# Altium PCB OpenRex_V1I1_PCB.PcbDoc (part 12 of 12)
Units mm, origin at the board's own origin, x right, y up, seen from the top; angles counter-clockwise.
Board outline 70 x 95 mm, 10 copper layers (L1, L2, L3, L4 (PWR), L5 (PWR), L6 (PWR), L7 (PWR), L8, L9, L10), stack 1.632 mm thick; 1080 components, 708 nets, 3831 pads, 2373 vias.
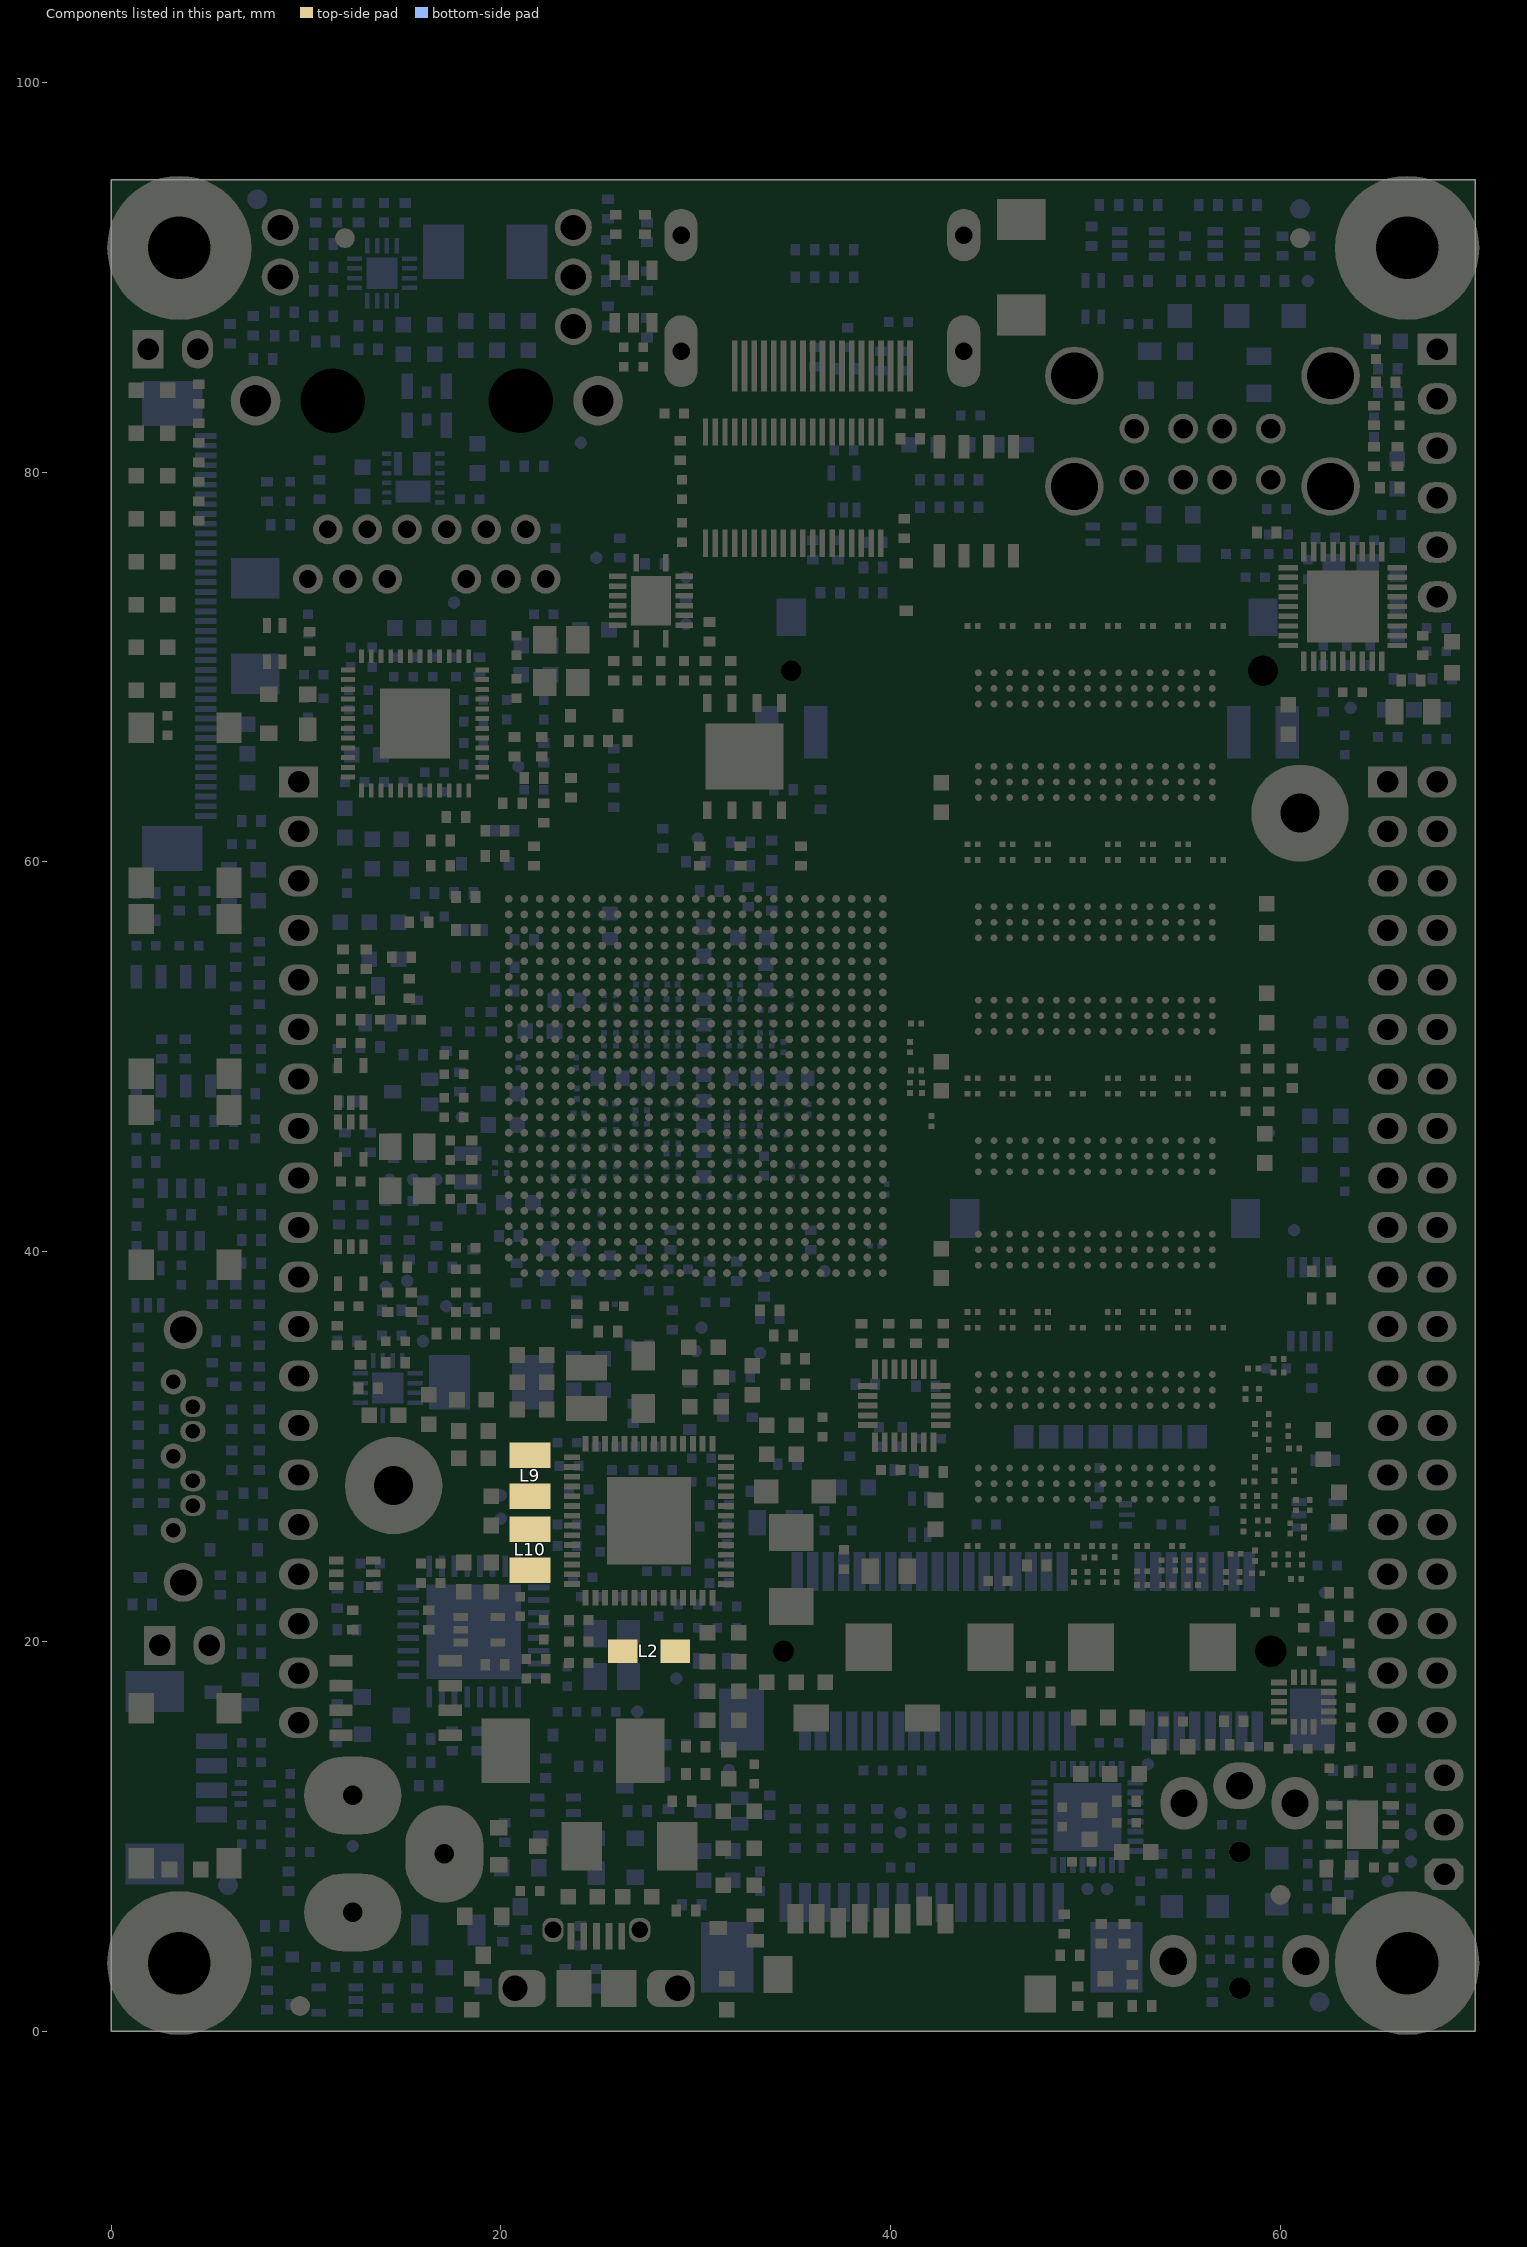
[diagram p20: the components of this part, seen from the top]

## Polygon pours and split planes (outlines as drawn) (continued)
GND on L10 "L10" (solid, remove dead copper, pour order 579): 23.6,30.5 24.1,30.5 24.3,30.3 24.5,30.3 25.2,30.3 25.2,29.7 25,29.5 24.7,29.2 24.25,28.75 23.7,28.75 23.7,29.4 23.6,29.5
+VIN_4V2 on L10 "L10" (solid, remove dead copper, pour order 578): 25.4,28.5 29.1,28.5 29.1,29 28.8,29 28.7,29.1 28.2,29.6 27.8,29.6 27.3,29.6 27.2,29.7 27.2,30.3 25.6,30.3 25.6,29.8 25.3,29.5 25.3,28.6
+3V3 on L10 "L10" (solid, remove dead copper, pour order 577): 38.2,29.8 38.2,29.2 37.9,29.2 37.8,29.1 37.8,27.5 36.9,27.5 36.9,29.8 38.2,29.8
+3V3_GYRO on L10 "L10" (solid, remove dead copper, pour order 576): 38.4,27.5 39.3,27.5 39.3,28 39.7,28.4 39.8,28.5 40.5,28.5 40.5,29.1 40.9,29.5 40.9,30.3 39.1,30.3 38.9,30.1 38.9,29.4 38.9,29.2 38.5,28.8 38.4,28.7
GND on L10 "L10" (solid, remove dead copper, pour order 575): 24.8,34.9 25.8,34.9 26.2,34.5 26.2,32.7 26,32.5 24.8,32.5
+1V375_SOC on L10 "L10" (solid, remove dead copper, pour order 574): 20.6,34.7 20.6,31.9 22.8,31.9 23.4,31.3 23.9,31.3 23.9,32.2 24.2,32.5 24.2,34.9 23.4,34.9 23.2,35.1 21,35.1 20.6,34.7
+VIN_4V2 on L10 "L10" (solid, remove dead copper, pour order 573): 15.4,32.3 14.9,31.8 14.9,31.6 14.7,31.6 14.4,31.6 14.3,31.5 14.3,30.8 14.4,30.7 15.3,30.7 16,31.4 16,32.3
PHASE_1V375 on L10 "L10" (solid, remove dead copper, pour order 572): 15.7,32.6 15.6,32.7 15.6,33.8 15.6,34 16.3,34.7 18.4,34.7 18.4,31.9 16.3,31.9 16.3,32.3 16,32.6 15.7,32.6 15.6,32.7
+VIN_5V on L10 "L10" (solid, remove dead copper, pour order 570): 19 vertices, not listed, extent 21.4,8.9 22.9,10.8
+3V3_MCU on L10 "L10" (solid, remove dead copper, pour order 569): 23.6,16.1 25.2,16.1 25.2,16.6 25,16.8 24.6,17.2 23.5,17.2 23.4,17.1 23.4,17 23.4,16.8 23.5,16.7 23.6,16.6
GND on L10 "L10" (solid, remove dead copper, pour order 568): 19.8,5.3 20.4,5.3 20.9,5.8 21.4,5.8 21.4,6.8 20.7,7.5 20.5,7.5 20,7 20,6.7 20,6.5 19.9,6.4 19.8,6.3 19.8,5.5
+V_INPUT on L10 "L10" (solid, remove dead copper, pour order 567): 16.3,4.4 16.3,6.5 16,6.8 15.4,6.8 15.1,6.5 15.1,4.4 16.3,4.4
GND on L10 "L10" (solid, remove dead copper, pour order 566): 21 vertices, not listed, extent 0.7,7.1 4.4,10.3
GND on L10 "L10" (solid, remove dead copper, pour order 565): 1.1,19.1 1.6,18.6 4,18.6 4.4,18.2 4.4,16.6 3.6,15.8 3.1,15.3 1.6,15.3 0.9,15.3 0.7,15.5 0.7,18.8 1,19.1
GND on L10 "L10" (solid, remove dead copper, pour order 564): 22 vertices, not listed, extent 0.4,59.2 5.2,62.4
SPLIT_R on L10 "L10" (solid, remove dead copper, pour order 563): 4.8,49.1 5.4,49.1 5.9,48.6 6.1,48.4 6.5,48.4 6.7,48.4 6.7,47.8 5.5,47.8 5.4,47.9 4.8,47.9 4.8,49.1
+3V3 on L10 "L10" (solid, remove dead copper, pour order 562): 7.2,58.4 8.2,58.4 8.5,58.1 8.5,57.7 7.7,56.9 7.5,56.9 7.2,57.2 7.1,57.3 7.1,58.4
+3V3_CSI1 on L10 "L10" (solid, remove dead copper, pour order 561): 4.8,63 4.8,62.2 5.3,62.2 5.4,62.1 5.6,61.9 5.6,59.3 5.6,57.6 6.5,57.6 6.5,61.3 6.2,61.6 6.2,62.2 6.2,62.4 5.6,63 4.8,63
GND on L10 "L10" (solid, remove dead copper, pour order 560): 6.9,61.2 7.5,61.2 8,60.7 8,59.1 7.5,58.6 7.1,58.6 7.1,59.8 7.1,60 7,60.1 6.9,60.2 6.9,61.2
GND on L10 "L10" (solid, remove dead copper, pour order 559): 28.9,39.4 28.9,37.7 28.3,37.7 28.3,38.3 27.8,38.8 27.8,39.3 27.9,39.4
GND on L10 "L10" (solid, remove dead copper, pour order 558): 19.6,42.9 20.5,42.9 20.5,42.2 20.8,41.9 20.9,41.8 20.9,41.6 20.8,41.5 19.9,41.5 19.6,41.8 19.6,42 19.6,42.9
+NVCC_CSI on L10 "L10" (solid, remove dead copper, pour order 557): 27 vertices, not listed, extent 29.5,39.2 32.7,43.5
+HDMI_VPH on L10 "L10" (solid, remove dead copper, pour order 556): 27 vertices, not listed, extent 28.7,39.2 31,44
+HDMI_VP on L10 "L10" (solid, remove dead copper, pour order 555): 29 vertices, not listed, extent 27.9,40.8 29,44
+NVCC_MIPI on L10 "L10" (solid, remove dead copper, pour order 554): 27.3,44 27.3,43.7 26.9,43.3 26.5,42.9 26.5,41.5 26.5,40.2 26.9,39.8 27.5,39.8 27.8,40.1 27.8,40.8 27.8,42.4 27.7,42.5 27.7,44
+2V5 on L10 "L10" (solid, remove dead copper, pour order 553): 35.6,40.4 36.8,40.4 37.7,39.5 37.7,39 37.6,38.9 37.4,38.7 36.5,38.7 35.6,39.6 35.6,40.4
GND on L10 "L10" (solid, remove dead copper, pour order 511): 45.4,94 48.2,94 48.6,93.6 48.6,92.3 48.2,91.9 45.4,91.9
PHASE_3V3_HDR on L10 "L10" (solid, remove dead copper, pour order 514): 15.35,89.85 18.1,89.85 18.1,92.7 16,92.7 15.4,92.1 15.3,92 15.3,90 15.3,89.9
+VIN_4V2 on L10 "L10" (solid, remove dead copper, pour order 515): 17 vertices, not listed, extent 14.05,86.8 17.6,89.55
GND on L10 "L10" (solid, remove dead copper, pour order 516): 14.6,86.5 15.4,86.5 15.6,86.3 15.8,86.3 16,86.3 16.2,86.5 17,86.5 17,85.6 16.7,85.3 15,85.3 14.9,85.3 14.6,85.6
GND on L10 "L10" (solid, remove dead copper, pour order 517): 19 vertices, not listed, extent 17.4,85.3 22.3,87
+3V3_HDR on L10 "L10" (solid, remove dead copper, pour order 518): 22 vertices, not listed, extent 17.8,87.3 22.4,92.7
GND on L10 "L10" (solid, remove dead copper, pour order 519): 25 vertices, not listed, extent 0.5,80.9 5.3,85.3
GND on L10 "L10" (solid, remove dead copper, pour order 520): 12,80.7 12,80.3 12.5,79.8 13.3,79.8 13.5,80 13.5,81.1 13.2,81.1 13.1,81.1 12.9,80.9 12.8,80.8 12.7,80.8 12.2,80.8 12,80.6
+3V3 on L10 "L10" (solid, remove dead copper, pour order 521): 11.5,80.8 11.6,80.7 11.6,80.5 11.5,80.4 11.4,80.3 10.5,80.3 10,80.3 9.8,80.5 9.8,80.7 10,80.9 10.3,80.9 11.4,80.9 11.5,80.8
+VIN_4V2 on L10 "L10" (solid, remove dead copper, pour order 522): 10.1,79.1 10.3,78.9 10.4,78.9 11.1,78.9 11.3,79.1 11.5,79.1 11.6,79 11.6,78.8 11.1,78.3 10.3,78.3 9.8,78.8 9.8,79 9.9,79.1
+VIN_ETH on L10 "L10" (solid, remove dead copper, pour order 523): 10.4,79.9 11.9,79.9 12.6,79.2 13.3,79.2 14,78.5 14,78.4 13.9,78.3 12.5,78.3 11.5,79.3 10.4,79.3
SW_EP on L10 "L10" (solid, remove dead copper, pour order 524): 13.9,81 13.9,81.1 15,81.1 15,79.8 14.5,79.8 14.4,79.7 14.4,79.4 14.4,79.3 13.9,79.3
+1V2_REG on L10 "L10" (solid, remove dead copper, pour order 525): 30 vertices, not listed, extent 15.5,78.3 20.5,81.1
+1V2_ETH on L10 "L10" (solid, remove dead copper, pour order 526): 20.9,80 21.5,80 21.5,80.6 21.8,80.9 21.8,81.1 21.7,81.2 20.7,81.2 20.6,81.1 20.6,80.9 20.9,80.6
+1V2_PMIC on L10 "L10" (solid, remove dead copper, pour order 527): 22,80 22,81.2 22.8,82 24.2,82 24.4,81.8 24.5,81.7 24.5,81.3 23.2,80
GND on L10 "L10" (solid, remove dead copper, pour order 528): 22.1,71.5 23.4,71.5 24.3,70.6 24.3,70.2 23.3,69.2 22.1,69.2
+1V2_ETH_AVDDL_PLL on L10 "L10" (solid, remove dead copper, pour order 529): 30 vertices, not listed, extent 18.8,66.9 22.5,70
GND on L10 "L10" (solid, remove dead copper, pour order 530): 9.8,67.1 10.4,67.1 10.9,67.6 10.9,67.8 10.7,68 10.3,68 10.2,68.1 10.2,68.7 9.6,68.7 9.6,67.3
+1V2_ETH_DVDDL on L10 "L10" (solid, remove dead copper, pour order 531): 44 vertices, not listed, extent 11.3,62.3 16.4,67.5
GND on L10 "L10" (solid, remove dead copper, pour order 532): 6.2,73.5 8.7,73.5 8.7,75.4 9.2,75.9 9.2,76.1 9.1,76.2 8,76.2 7.4,76.2 6.8,75.6 6.2,75.6
+5V_HDR_J1 on L10 "L10" (solid, remove dead copper, pour order 533): 22 vertices, not listed, extent 6.2,63.3 10.6,70.7
+5V on L10 "L10" (solid, remove dead copper, pour order 534): 7.3,68.1 7.5,68.1 8,67.6 8,67.2 7.4,66.6 6.9,66.6 6.6,66.6 6.6,67.4
+VIN_5V on L10 "L10" (solid, remove dead copper, pour order 535): 7.4,63.6 7.4,64.5 6.4,64.5 6,64.9 5.7,64.9 5.7,63.8 5.9,63.6
+3V3 on L10 "L10" (solid, remove dead copper, pour order 536): 14.3,56.5 15.2,56.5 15.2,57.9 13.8,57.9 13.8,57.6 13.9,57.5 14,57.4 14.2,57.4 14.3,57.3
+3V3_HDR on L10 "L10" (solid, remove dead copper, pour order 537): 11.1,55.9 12.1,55.9 12.2,56 12.2,57.3 11.3,57.3 11.1,57.1 11.1,55.9
+3V3_HDR_J1 on L10 "L10" (solid, remove dead copper, pour order 538): 19 vertices, not listed, extent 9.1,48.3 13.7,57.3
GND on L10 "L10" (solid, remove dead copper, pour order 539): 14.3,55.4 14.8,55.4 15.2,55.8 15.6,55.8 15.6,54.7 15,54.1 14.4,54.1 14.3,54.2 14.3,55.4
GND on L10 "L10" (solid, remove dead copper, pour order 540): 21.7,51.7 21.7,50.9 20.7,50.9 20.2,50.4 20.1,50.3 20,50.3 19.8,50.5 19.8,50.7 20.2,51.1 20.8,51.7 21.7,51.7
+1V375_CORE on L10 "Power plane" (solid, pour order 411): 21 vertices, not listed, extent 27.8,44.8 33,45.5
GND on L10 "Power plane" (solid, pour order 414): 23 vertices, not listed, extent 26.7,44.7 29.7,46.3
+1V2_VDD_ARM_CAP on L10 "Power plane" (solid, pour order 421): 29 vertices, not listed, extent 26.2,46.05 31.8,46.8
GND on L10 "Power plane" (solid, pour order 425): 23 vertices, not listed, extent 25.7,46.6 28.9,48.2
GND on L10 "Power plane" (solid, pour order 433): 27 vertices, not listed, extent 28.5,47.2 32.2,49.4
GND on L10 "Power plane" (solid, pour order 437): 31.2,47.3 32.6,47.3 33.5,47.3 33.5,47.2 33.5,46.3 32.9,46.3 32.1,46.3 32.1,46.7 31.9,46.9 31.6,46.9 31.4,46.9 31.2,47.1
+1V1_VDDSOC_CAP on L10 "Power plane" (solid, pour order 442): 19 vertices, not listed, extent 32.1,47.5 33.5,50.2
+1V375_CORE on L10 "Power plane" (solid, pour order 446): 23 vertices, not listed, extent 25.7,48.5 29.8,50.2
+1V2_VDD_ARM_CAP on L10 "Power plane" (solid, pour order 450): 26.2,48.1 26.2,48.2 26.3,48.3 26.4,48.3 27,48.3 27.1,48.4 27.1,49.3 27.3,49.3 27.9,49.3 27.9,48.5 28.1,48.3 28.1,48 28,47.9 27.7,47.6 26.7,47.6
GND on L10 "Power plane" (solid, pour order 453): 31 vertices, not listed, extent 24.7,50.3 29.8,51.4
GND on L10 "Power plane" (solid, pour order 455): 17 vertices, not listed, extent 31.1,50.3 35.4,50.9
+1V375_SOC on L10 "Power plane" (solid, pour order 456): 62 vertices, not listed, extent 23.7,50.6 33.5,53.3
+VDDPU on L10 "Power plane" (solid, pour order 458): 30 vertices, not listed, extent 25.7,51.4 30.8,52.8
GND on L10 "Power plane" (solid, pour order 459): 40 vertices, not listed, extent 24.6,52.6 30.8,53.9
GND on L10 "Power plane" (solid, pour order 462): 26 vertices, not listed, extent 34.5,45.8 36.1,49.3
GND on L10 "L10" (solid, remove dead copper, pour order 541): 25.3,48.5 25.3,49.3 24.3,49.3 24,49.6 23.7,49.6 23.7,48.2 24.1,48.2 24.2,48.2 24.5,48.5 25.3,48.5
+3V3 on L10 "L10" (solid, remove dead copper, pour order 542): 25 vertices, not listed, extent 22.3,49.6 25.5,51.9
+3V3 on L10 "L10" (solid, remove dead copper, pour order 543): 27 vertices, not listed, extent 27.3,53.55 30.8,55.55
GND on L10 "L10" (solid, remove dead copper, pour order 544): 32.95,53.55 32.95,54.2 33.15,54.4 34,54.4 34.05,54.45 34.05,56.5 33.25,56.5 33.25,55.75 32.9,55.4 32.45,54.95 32.45,53.9 32.45,53.75 32.65,53.55
+1V5_DDR on L10 "L10" (solid, remove dead copper, pour order 545): 21 vertices, not listed, extent 31.05,52.25 34,53.8
GND on L10 "L10" (solid, remove dead copper, pour order 546): 27 vertices, not listed, extent 31.1,51.6 35.1,53.3
+1V5_DDR on L10 "L10" (solid, remove dead copper, pour order 547): 34.75,52.8 34.25,52.3 34.25,51.9 34.25,51.6 34.05,51.4 33.75,51.4 33.75,51.05 34.45,51.05 34.6,51.2 34.9,51.5 34.9,52 34.9,52.3 35.05,52.45 35.05,52.8
+LVDS_2V5 on L10 "L10" (solid, remove dead copper, pour order 548): 25 vertices, not listed, extent 33.2,40.8 36.2,44.2
+1V5_DDR on L10 "L10" (solid, remove dead copper, pour order 549): 28 vertices, not listed, extent 33.7,44.2 35.1,50.4
GND on L10 "Power plane" (solid, pour order 409): 46 vertices, not listed, extent 25.7,42.6 33,45
GND on L10 "L10" (solid, remove dead copper, pour order 550): 25 vertices, not listed, extent 24.1,44.2 25.5,46.4
GND on L10 "L10" (solid, remove dead copper, pour order 551): 23.9,44 23.9,42.9 23.3,42.9 22.5,43.7 22.5,44 22.9,44 23.1,44.2 23.3,44.2 23.4,44.1 23.5,44 23.9,44
+1V1_NVCC_PLL_OUT on L10 "L10" (solid, remove dead copper, pour order 552): 21 vertices, not listed, extent 20.9,42.1 23.4,45
GND on L10 "L10" (solid, remove dead copper, pour order 397): 24.7,13.9 25.2,13.9 25.5,14.2 26.8,14.2 26.8,13.5 26,13.5 25.8,13.3 25.1,12.6 24.6,12.6 24.5,12.6 24.4,12.7 24.4,12.9 24.4,13 24.7,13.3
GND on L10 "L10" (solid, remove dead copper, pour order 400): 26.4,10.3 26.4,9.5 26.7,9.2 27.2,8.7 27.7,8.7 27.8,8.8 27.8,10.3 27.6,10.5 26.6,10.5 26.4,10.3
GND on L10 "L10" (solid, remove dead copper, pour order 319): 48.5,24.6 49.5,24.6 49.6,24.5 49.6,24.2 49.2,23.8 49.1,23.7 49.1,23.5 48.5,23.5
GND on L2 (split plane): 69.898,0.102 0.102,0.102 0.102,94.898 69.898,94.898
GND on L9 (split plane): 69.898,0.102 0.102,0.102 0.102,94.898 69.898,94.898

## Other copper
L10:
  rectangle net PWM2_OUT_R: 61.7,50.3 62.35,50.95
  region net UART4_TXD: 63.5,50.95 62.85,50.95 62.85,50.3 63.5,50.3
  region net UART4_TXD_R: 62.85,52.1 62.85,51.45 63.5,51.45 63.5,52.1
  region net GPIO_OR_PWM_2: 61.7,52.1 61.7,51.45 62.35,51.45 62.35,52.1
  region: 1344 vertices and 0 holes, not listed, extent 31.797,93.426 33.878,94.403
  region: 1381 vertices and 0 holes, not listed, extent 32.34,91.702 33.939,93.239
  region: 2099 vertices and 0 holes, not listed, extent 30.813,91.665 32.707,94.4

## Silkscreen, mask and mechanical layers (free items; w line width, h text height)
Top Overlay:
  text ".VersionRevision" at 52.7,77.2 h2.5 r180
  text "5" at 4.7,75.9 h2.2 r270
  text ".Project" at 57,74.8 h3.35 r180
  text "6" at 4.7,73.7 h2.2 r270
  text "7" at 4.7,71.5 h2.2 r270
  text "8" at 4.7,69.3 h2.2 r270
  text "+" at 3.1,57.8 h3
  text "(c) 2016" at 61.8,52 h2.2 r90
  text "-" at 3,49.6 h3.5 r270
  text "FEDEVEL Academy" at 63.5,41 h2.2 r90
  text "H" at 3,39.9 h2.5 r270
  text "R" at 3,17.5 h2.5 r270
Bottom Overlay:
  lines w0.254: 26.644,77.999 26.644,80.499 ; 29.644,77.999 29.644,80.499 ; 32.644,77.999 32.644,80.499 ; 23.644,77.999 35.644,77.999 35.644,80.499 23.644,80.499 23.644,77.999
  text "MODBOX" at 35.6,81.5 h2.3
  text "D" at 25.944,78.499 h2.5
  text "C" at 28.944,78.499 h2.5
  text "B" at 31.944,78.499 h2.5
  text "A" at 34.944,78.499 h2.5
  text "Learn Schematic" at 55.8,68 h2.5
  text "and PCB Design" at 55.6,65.4 h2.5
  text "ONLINE at" at 52.4,62.8 h2.5
  text "FEDEVEL Academy" at 57.3,60.2 h2.5
  text "Do you want to learn how to" at 59.8,55 h2
  text "design boards like this?" at 58.2,52.7 h2
  text "Go to: fedevel.com/academy" at 60.2,50.4 h2
Bottom Paste:
  rectangle: 61.7,51.45 62.35,52.1
  rectangle: 62.85,51.45 63.5,52.1
  rectangle: 62.85,50.3 63.5,50.95
  rectangle: 61.7,50.3 62.35,50.95
Bottom Solder:
  drawing of 7 lines, arcs and shapes, not listed
Manufacturing Notes:
  circle w1: c176.75,149.25 r0.25
  circle w1: c176.75,108.25 r0.25
  circle w1: c260.75,108.25 r0.25
  circle w1: c260.75,149.25 r0.25
  lines w0.2: 142.5,102.5 178.75,102.5 ; 142.5,105 178.75,105 ; 142.5,152.5 178.75,152.5 ; 142.5,155 178.75,155 ; 144,101.5 145,102.5 146,101.5 ; 144,106 145,105 146,106 ; 144,151.5 145,152.5 146,151.5 ; 144,156 145,155 146,156 ; 145,95 145,162.5 ; 163.75,128.75 165,128.75 ; 175,108.75 176.25,108.75 ; 175,148.75 176.25,148.75 ; 176.25,110 176.25,108.75 ; 176.25,147.5 176.25,148.75 ; 180,108.75 180,110 ; 180,152.5 180,164 ; 181,161.5 180,162.5 ; 181,163.5 180,162.5 ; 181.25,110 180,110 ; 197.5,91 197.5,92.5 ; 213.75,102.5 213.75,103.75 ; 213.75,110 215,110 ; 213.75,155 213.75,153.75 ; 214,161.5 215,162.5 ; 214,163.5 215,162.5 ; 215,102.5 227.5,102.5 ; 215,103.75 213.75,103.75 ; 215,105 227.5,105 ; 215,108.75 215,110 ; 215,153.75 213.75,153.75 ; 215,155 227.5,155 ; 215,164 215,152.5 227.5,152.5 ; 218.75,93.75 218.75,98.75 ; 218.75,163.75 218.75,158.75 ; 222.5,103.75 223.75,103.75 ; 222.5,108.75 222.5,110 ; 222.5,152.5 222.5,164 ; 222.5,153.75 223.75,153.75 ; 223.5,161.5 222.5,162.5 ; 223.5,163.5 222.5,162.5 ; 223.75,102.5 223.75,103.75 ; 223.75,110 222.5,110 ; 223.75,155 223.75,153.75 ; 240,91 240,92.5 ; 256.25,110 257.5,110 ; 256.5,161.5 257.5,162.5 ; 256.5,163.5 257.5,162.5 ; 257.5,108.75 257.5,110 ; 257.5,152.5 257.5,164 ; 261.25,110 261.25,108.75 ; 261.25,147.5 261.25,148.75 ; 262.5,108.75 261.25,108.75 ; 262.5,148.75 261.25,148.75 ; 282.5,128.75 281.25,128.75 ; 165,128.75 167,126.75 ; 165,128.75 167,130.75 167,139.5 176.25,148.75 ; 167,126.75 167,118 176.25,108.75 ; 167,126.75 167,126.75 ; 180,110 197.5,92.5 ; 180,162.5 215,162.5 ; 197.5,92.5 215,110 ; 213.75,103.75 218.75,98.75 ; 213.75,153.75 218.75,158.75 ; 218.75,98.75 223.75,103.75 ; 218.75,158.75 223.75,153.75 ; 222.5,110 240,92.5 ; 222.5,162.5 257.5,162.5 ; 240,92.5 257.5,110 ; 261.25,108.75 281.25,128.75 ; 261.25,148.75 281.25,128.75
  lines w0.254: -6.5,-82 86,-82 ; -6.5,-81.925 -6.5,-71.925 ; -6.5,-62 86,-62 ; 33.5,-72 33.5,-62 ; 68.5,-62 68.5,-54.5 ; 86,-81.925 86,-71.925 ; -6.5,-72 -6.5,-54.5 86,-54.5 86,-72 -6.5,-72
  lines w0.4: 142.524,54.2 291.976,54.2 ; 142.524,61.16 291.976,61.16 ; 291,70.5 143.25,70.5 ccw(c143.25,68.25) 141,68.25 141,-34.75 ccw(c143.25,-34.75) 143.25,-37 291.25,-37 ccw(c291.25,-34.75) 293.5,-34.75 293.5,68.25 ccw(c291.25,68.25) 291.25,70.5
  lines w0.5: 180,100 180,102.5 ; 180,105 180,152.5 ; 180,155 180,157.5 ; 215,100 215,102.5 ; 215,105 215,152.5 ; 215,155 215,157.5 ; 216.096,102.5 ccw(c216.096,103.75) 216.096,105 ; 216.096,152.5 ccw(c216.096,153.75) 216.096,155 ; 216.25,102.5 178.75,102.5 cw(c178.75,103.75) 178.75,105 216.25,105 ; 216.25,152.5 178.75,152.5 cw(c178.75,153.75) 178.75,155 216.25,155 ; 221.25,102.5 258.75,102.5 ccw(c258.75,103.75) 258.75,105 221.25,105 ; 221.25,152.5 258.75,152.5 ccw(c258.75,153.75) 258.75,155 221.25,155 ; 221.404,102.5 cw(c221.404,103.75) 221.404,105 ; 221.404,152.5 cw(c221.404,153.75) 221.404,155 ; 222.5,100 222.5,102.5 ; 222.5,105 222.5,152.5 ; 222.5,155 222.5,157.5 ; 257.5,100 257.5,102.5 ; 257.5,105 257.5,152.5 ; 257.5,155 257.5,157.5 ; 263.75,100 173.75,100 173.75,157.5 263.75,157.5 263.75,100.154
  text "Board info" at 141,258 h1.52
  text "Minimum Track: 100um" at 141,255.5 h1.52
  text "Minimum Gap: 100um" at 141,253 h1.52
  text "Minimum Through Hole VIA: 0.45mm (pad) / 0.2mm (drill). Drilling: L1-L10" at 141,250.5 h1.52
  text "1. REMOVE ALL NON-FUNCTIONAL INNER LAYER PADS." at 141,245.5 h1.52
  text "2. THIS BOARD CONTAINS IMPEDANCE CONTROLLED TRACKS, TRACK AND GAP SIZES ARE AS FOLLOWS:" at 141,240.5 h1.52
  text "TYPE;" at 146,235.5 h1.52
  text "Impedance;" at 158.5,235.5 h1.52
  text "Layer (Reference);" at 181,235.5 h1.52
  text "Width (um);" at 216,235.5 h1.52
  text "Gap (um);" at 236,235.5 h1.52
  text "DIFF;" at 146,230.5 h1.52
  text "90ohm;" at 158.5,230.5 h1.52
  text "L1(L2), L10(L9);" at 181,230.5 h1.52
  text "114" at 216,230.5 h1.52
  text "160" at 236,230.5 h1.52
  text "DIFF;" at 146,228 h1.52
  text "90ohm;" at 158.5,228 h1.52
  text "L3(L2,L4), L8(L9,L7);" at 181,228 h1.52
  text "130" at 216,228 h1.52
  text "190" at 236,228 h1.52
  text "DIFF;" at 146,223 h1.52
  text "100ohm;" at 158.5,223 h1.52
  text "L1(L2), L10(L9);" at 181,223 h1.52
  text "100" at 216,223 h1.52
  text "220" at 236,223 h1.52
  text "DIFF;" at 146,220.5 h1.52
  text "100ohm;" at 158.5,220.5 h1.52
  text "L3(L2,L4), L8(L9,L7);" at 181,220.5 h1.52
  text "110" at 216,220.5 h1.52
  text "210" at 236,220.5 h1.52
  text "SE;" at 146,215.5 h1.52
  text "50ohm;" at 158.5,215.5 h1.52
  text "L1(L2), L10(L9);" at 181,215.5 h1.52
  text "114" at 216,215.5 h1.52
  text "SE;" at 146,213 h1.52
  text "50ohm;" at 158.5,213 h1.52
  text "L3(L2,L4), L8(L9,L7);" at 181,213 h1.52
  text "120" at 216,213 h1.52
  text "3. FINISHED PANEL THICKNESS IS NOT CRITICAL: TO BE APPROXIMATELY 1.6mm" at 141,208 h1.52
  text "4. BOARD FINISH: IMMERSION Au/ELECTROLESS Ni; 0.05-0.12 um GOLD; 3-6um NICKEL" at 141,203 h1.52
  text "5. SOLDER RESIST: APPLY TO BOTH SIDES COLOUR - NAVY BLUE" at 141,198 h1.52
  text "6. COMPONENT IDENT: COLOUR TO BE WHITE" at 141,193 h1.52
  text "7. PANELIZE THE BOARD (2PCS PER PANEL). PLACE FIDUCIALS ON THE PANEL STRIPS AS FOLLOWS:" at 141,188 h1.52
  text "- FIDUCIAL DIAMTER 1-1.5MM, SOLDER MASK OPENING AT LEAST 1MM GREATER THAN FIDUCIAL" at 146,185.5 h1.52
  text "- MINIMUM 4MM DISTANCE FROM THE PANEL EDGE" at 146,183 h1.52
  text "- 3 FIDUCIALS SHOULD LIE ON TWO LINES THAT INTERSECT AT A RIGHT ANGLE" at 146,180.5 h1.52
  text "- PLACE ONE FIDUCIAL INTO EACH PANEL CORNER (FOUR ON THE TOP AND FOUR ON THE BOTTOM LAYER)" at 146,178 h1.52
  text "PANEL DRAWING (NOT IN SCALE):" at 145.254,172.754 h1.52
  text "- NOT SPECIFIED DIMENSIONS ARE NOT CRITICAL. CAN BE CHOSEN BY PCB MANUFACTURER" at 145.254,170.254 h1.52
  text "CUT-OUT" at 214.004,165.254 h1.52
  text "70mm" at 194.75,163.75 h1.52
  text "70mm" at 237.25,163.75 h1.52
  text "5mm" at 143.75,157.5 h1.52 r90
  text "Files" at -4,150.5 h1.52
  text "*.GTO - Top Overlay" at -4,148 h1.52
  text "*.GTP - Top Paste" at -4,145.5 h1.52
  text "*.GTS - Top Solder" at -4,143 h1.52
  text "*.GTL - L1 (Positive)" at -4,140.5 h1.52
  text "*.GP1 - L2 (Negative)" at -4,138 h1.52
  text "*.G1 - L3 (Positive)" at -4,135.5 h1.52
  text "*.G2 - L4 (PWR) (Positive)" at -4,133 h1.52
  text "*.G3 - L5 (PWR) (Positive)" at -4,130.5 h1.52
  text "FIDUCIALS" at 148.354,128.404 h1.52
  text "*.G4 - L6 (PWR) (Positive)" at -4,128 h1.52
  text "FIDUCIALS" at 285.354,127.654 h1.52
  text "PCB" at 190,127.5 h5.08
  text "PCB" at 232.5,127.5 h5.08
  text "95mm" at 143.75,126.25 h1.52 r90
  text "*.G5 - L7 (PWR) (Positive)" at -4,125.5 h1.52
  text "*.G6 - L8 (Positive)" at -4,123 h1.52
  text "*.GP2 - L9 (Negative)" at -4,120.5 h1.52
  text "*.GBL - L10 (Positive)" at -4,118 h1.52
  text "*.GBS - Bottom Solder" at -4,115.5 h1.52
  text "*.GBP - Bottom Paste" at -4,113 h1.52
  text "*.GBO - Bottom Overlay" at -4,110.5 h1.52
  text "*.GM3 - Manufacturing Notes" at -4,108 h1.52
  text "*.GM4 - License" at -4,105.5 h1.52
  text "*.GM6 - Mechanical Drawing" at -4,103 h1.52
  text "*.GM28 - Board Outline" at -4,100.5 h1.52
  text "5mm" at 143.75,96.25 h1.52 r90
  text "CUT-OUT" at 213.75,91.25 h1.52
  text "V-CUT" at 194.104,87.654 h1.52
  text "V-CUT" at 236.604,87.654 h1.52
  text "Layer Stack Up Detail for: OpenRex V1I1_PCB.PcbDoc" at 142.524,64.75 h1.6
  text "Layer" at 142.524,58.56 h1.6
  text "Gerber" at 187.629,58.56 h1.6
  text "Copper" at 210.818,58.56 h1.6
  text "Dielectric" at 234.119,58.56 h1.6
  text "Dielectric" at 261.619,58.56 h1.6
  text "Name" at 142.524,55.36 h1.6
  text "Document" at 187.629,55.36 h1.6
  text "Thickness" at 210.818,55.36 h1.6
  text "Height" at 234.119,55.36 h1.6
  text "Constant" at 261.619,55.36 h1.6
  text "Top Solder Mask" at 142.524,50.193 h2.25
  text "(.GTS)" at 187.629,50.193 h2.25
  text "43um" at 212.629,42.693 h2.25
  text "L1" at 142.524,42.578 h2.25
  text "(.GTL)" at 187.629,42.578 h2.25
  text "74um" at 235.129,38.943 h2.25
  text "3.95" at 262.629,38.943 h2.25
  text "18um" at 212.629,35.193 h2.25
  text "L2" at 142.524,34.963 h2.25
  text "(.GP1)" at 187.629,34.963 h2.25
  text "102um" at 235.129,31.443 h2.25
  text "4.12" at 262.629,31.443 h2.25
  text "18um" at 212.629,27.693 h2.25
  text "L3" at 142.524,27.348 h2.25
  text "(.G1)" at 187.629,27.348 h2.25
  text "282um" at 235.129,23.943 h2.25
  text "4.06" at 262.629,23.943 h2.25
  text "18um" at 212.629,20.193 h2.25
  text "L4 (PWR)" at 142.524,19.733 h2.25
  text "(.G2)" at 187.629,19.733 h2.25
  text "102um" at 235.129,16.443 h2.25
  text "4.12" at 262.629,16.443 h2.25
  text "18um" at 212.629,12.693 h2.25
  text "L5 (PWR)" at 142.524,12.233 h2.25
  text "(.G3)" at 187.629,12.233 h2.25
  text "282um" at 235.129,8.943 h2.25
  text "4.06" at 262.629,8.943 h2.25
  text "18um" at 212.629,5.193 h2.25
  text "L6 (PWR)" at 142.524,4.733 h2.25
  text "(.G4)" at 187.629,4.733 h2.25
  text "102um" at 235.129,1.443 h2.25
  text "4.12" at 262.629,1.443 h2.25
  text "18um" at 212.629,-2.307 h2.25
  text "L7 (PWR)" at 142.524,-2.652 h2.25
  text "(.G5)" at 187.629,-2.652 h2.25
  text "282um" at 235.129,-6.057 h2.25
  text "4.06" at 262.629,-6.057 h2.25
  text "18um" at 212.629,-9.807 h2.25
  text "L8" at 142.524,-10.267 h2.25
  text "(.G6)" at 187.629,-10.267 h2.25
  text "102um" at 235.129,-13.557 h2.25
  text "4.12" at 262.629,-13.557 h2.25
  text "18um" at 212.629,-17.307 h2.25
  text "L9" at 142.524,-17.882 h2.25
  text "(.GP2)" at 187.629,-17.882 h2.25
  text "74um" at 235.129,-21.057 h2.25
  text "3.95" at 262.629,-21.057 h2.25
  text "43um" at 212.9,-24.6 h2.25
  text "L10" at 142.524,-25.497 h2.25
  text "(.GBL)" at 187.629,-25.497 h2.25
  text "Bottom Solder Mask" at 142.524,-33.112 h2.25
  text "(.GBS)" at 187.629,-33.112 h2.25
  text "OpenRex" at -3.5,-59.5 h3
  text ".VersionRevision" at 71,-59.5 h3
  text "Copyright 2016" at -1.5,-67 h1.52
  text "Designed by FEDEVEL" at 38.5,-67 h1.52
  text "FEDEVEL" at -1.5,-69.5 h1.52
  text "www.fedevel.com" at 38.5,-69.5 h1.52
  text "Contact:" at -1.5,-77 h1.52
  text "robert.feranec@fedevel.com" at 13.5,-77 h1.52
License:
  text "LICENSE" at -9,280.5 h1.52
  text "OpenRex is a registered trademark of FEDEVEL." at -9,275.5 h1.52
  text "This project is developed under Creative Commons Attribution 4.0 International license." at -9,270.5 h1.52
  text "There is one exception:" at -9,268 h1.52
  text "Using this project (in whole or in part) or its modifications for any commercial" at -9,263 h1.52
  text "educational activities (e.g. paid courses, trainings, videos, ....)  without express" at -9,260.5 h1.52
  text "written permission of FEDEVEL is prohibited. Universities can use this project" at -9,258 h1.52
  text "with no limitations." at -9,255.5 h1.52
  text "Why this exception?" at -9,250.5 h1.52
  text "The income from FEDEVEL courses covers development of open source boards like this." at -9,248 h1.52
  text "Creative Commons Attribution 4.0 International license" at -9,243 h1.52
  text "ORIGINAL AUTHOR: FEDEVEL 2016" at -9,238 h1.52
  text "WEBSITE: http://www.iMX6Rex.com" at -9,235.5 h1.52
  text "This is a human-readable summary of (and not a substitute for) the Legal Code" at -9,230.5 h1.52
  text "(read full license at: http://creativecommons.org/licenses/by/4.0/legalcode)." at -9,228 h1.52
  text "You are free:" at -9,223 h1.52
  text "Share - copy and redistribute the material in any medium or format" at -9,220.5 h1.52
  text "Adapt - remix, transform, and build upon the material for any purpose, even commercially." at -9,218 h1.52
  text "The licensor cannot revoke these freedoms as long as you follow the license terms." at -9,213 h1.52
  text "Under the following conditions:" at -9,208 h1.52
  text "Attribution - You must give appropriate credit, provide a link to the license," at -9,205.5 h1.52
  text "and indicate if changes were made. You may do so in any reasonable manner," at -9,203 h1.52
  text "but not in any way that suggests the licensor endorses you or your use." at -9,200.5 h1.52
  text "No additional restrictions - You may not apply legal terms or technological measures" at -9,198 h1.52
  text "that legally restrict others from doing anything the license permits." at -9,195.5 h1.52
  text "Notices:" at -9,190.5 h1.52
  text "You do not have to comply with the license for elements of the material in the public" at -9,188 h1.52
  text "domain or where your use is permitted by an applicable exception or limitation." at -9,185.5 h1.52
  text "No warranties are given. The license may not give you all of the permissions" at -9,180.5 h1.52
  text "necessary for your intended use. For example, other rights such as publicity, privacy," at -9,178 h1.52
  text "or moral rights may limit how you use the material." at -9,175.5 h1.52
Mechanical Drawing:
  circle w2.8: c11.374,83.657 r0.25
  circle w2.8: c21.026,83.657 r0.25
  circle w0.6: c57.9,2.2 r0.25
  circle w0.6: c57.9,9.2 r0.25
  circle w0.6: c34.5,19.5 r0.25
  circle w0.8: c59.5,19.5 r0.4
  circle w0.8: c59.1,69.8 r0.375
  circle w0.6: c34.9,69.8 r0.225
  circle w0.6: c61,62.5 r1
  circle w1: c66.5,91.5 r1.6
  circle w0.6: c14.5,28 r1
  circle w1: c3.5,91.5 r1.6
  circle w1: c3.5,3.5 r1.6
  circle w1: c66.5,3.5 r1.6
  lines w0.254: 3.3,12.6 4.3,12.6 ; 3.3,43.3 4.3,43.3 ; 3.3,53.1 4.3,53.1 ; 3.3,62.9 4.3,62.9 ; 3.8,12.1 3.8,13.1 ; 3.8,42.8 3.8,43.8 ; 3.8,52.6 3.8,53.6 ; 3.8,62.4 3.8,63.4 ; 4.4,72.1 4.85,72.1 ; 4.6,13 5.15,13 ; 16.2,76.353 16.2,77.684 ; 36.5,83.5 36.5,84.07 ; 56,79 56,80.1
  lines w1: 0,0 70,0 70,95 0,95 0,0 ; 11.5,23 11.5,72 63.5,72 63.5,23 11.5,23
  text "Mechanical Drawing" at 6.5,165.5 h3.5
  text "of OpenRex" at 11.5,155.5 h3.5
  text ".VersionRevision" at 49,155.5 h3.5
  text "Suggested heatsink dimensions" at 25,74 h1.5
  text "(Scale 1:1)" at 27.5,-57.5 h1.52
Board Outline:
  the board outline again, w0.2
ASM Top:
  lines w0.01: 106.9,50 106.9,50.05
  lines w0.2: -22,32.5 -7,32.5 ; -19.5,32.5 -19.5,37.5 -16.5,37.5 -16.5,32.5 ; -18.5,32.5 -18.5,28.5 -17.5,28.5 -17.5,32.5
  text "Assembly TOP of OpenRex" at 16,102 h1.52
  text ".VersionRevision" at 52.3,102 h1.52
  text ".VariantName" at 27.5,98 h1.52
  text "IMPORTANT:" at -22,45 h1.5
  text "PLACE J1 PLASTIC" at -22,42.5 h1
  text "SIDE ON THE TOP" at -22,40 h1
  text "TOP" at -11.55,33.5 h1
  text "BOTTOM" at -14.75,29.5 h1
ASM Bottom:
  rectangle: -17.7,64.3 -13.6,66.3
  rectangle: -17.7,60.3 -13.6,62.3
  rectangle: -15.6,89.3 -13.6,90.3
  rectangle: -15.6,85.3 -13.6,86.3
  region: -15.6,73.8 -17.6,73.8 -17.6,72.8 -15.6,72.8
  region: -15.6,77.8 -17.6,77.8 -17.6,76.8 -15.6,76.8
  lines w0.01: -36.9,50 -36.9,50.05
  lines w0.2: 77.4,33 92.5,33 ; 87.5,33 87.5,28 90.5,28 90.5,33 ; 88.5,33 88.5,37 89.5,37 89.5,33 ; -35,57.5 -35,97.5 -7.5,97.5 -7.5,57.5 -35,57.5 ; -19.1,59.4 -19.1,63.2 -12.3,63.2 -12.3,59.4 -19.1,59.4 ; -19.1,63.4 -19.1,67.2 -12.3,67.2 -12.3,63.4 -19.1,63.4 ; -19.1,71.9 -19.1,75.7 -12.3,75.7 -12.3,71.9 -19.1,71.9 ; -19.1,75.9 -19.1,79.7 -12.3,79.7 -12.3,75.9 -19.1,75.9 ; -19.1,84.4 -12.3,84.4 -12.3,88.2 -19.1,88.2 -19.1,84.4 ; -19.1,88.4 -12.3,88.4 -12.3,92.2 -19.1,92.2 -19.1,88.4 ; -18.4,60 -18.4,62.6 -16.9,62.6 -16.9,60 -18.4,60 ; -18.4,64 -18.4,66.6 -16.9,66.6 -16.9,64 -18.4,64 ; -18.4,72.5 -16.9,72.5 -16.9,75.1 -18.4,75.1 -18.4,72.5 ; -18.4,76.5 -18.4,79.1 -16.9,79.1 -16.9,76.5 -18.4,76.5 ; -18.4,85 -18.4,87.6 -16.9,87.6 -16.9,85 -18.4,85 ; -18.4,89 -16.9,89 -16.9,91.6 -18.4,91.6 -18.4,89 ; -16.4,60 -16.4,61.7 -14.9,61.7 -14.9,60 -16.4,60 ; -16.4,64 -16.4,65.7 -14.9,65.7 -14.9,64 -16.4,64 ; -16.4,72.5 -14.9,72.5 -14.9,74.2 -16.4,74.2 -16.4,72.5 ; -16.4,76.5 -16.4,78.2 -14.9,78.2 -14.9,76.5 -16.4,76.5 ; -16.4,85 -16.4,86.7 -14.9,86.7 -14.9,85 -16.4,85 ; -16.4,89 -14.9,89 -14.9,90.7 -16.4,90.7 -16.4,89 ; -14.4,60 -14.4,62.6 -12.9,62.6 -12.9,60 -14.4,60 ; -14.4,64 -12.9,64 -12.9,66.6 -14.4,66.6 -14.4,64 ; -14.4,72.5 -14.4,75.1 -12.9,75.1 -12.9,72.5 -14.4,72.5 ; -14.4,76.5 -12.9,76.5 -12.9,79.1 -14.4,79.1 -14.4,76.5 ; -14.4,85 -12.9,85 -12.9,87.6 -14.4,87.6 -14.4,85 ; -14.4,89 -14.4,91.6 -12.9,91.6 -12.9,89 -14.4,89
  text ".VersionRevision" at 14.5,102 h1.52
  text "Assembly BOTTOM of OpenRex" at 55.2,102 h1.52
  text ".VariantName" at 43.5,98 h1.52
  text "FITTING OPTION 1" at -9.9,93.8 h1
  text "FIT 2X 0402" at -22.5,87.5 h1
  text "FITTING OPTION 2" at -9.9,81.3 h1
  text "FIT 2X 0402" at -22.5,75 h1
  text "FITTING OPTION 3" at -9.9,68.8 h1
  text "FIT 2X 0805" at -22.5,62.5 h1
  text "IMPORTANT:" at 94,45 h1.5
  text "PLACE J2 PLASTIC" at 94,42.5 h1
  text "SIDE ON THE BOTTOM" at 94,40 h1
  text "TOP" at 86.35,34 h1
  text "BOTTOM" at 86.25,30 h1

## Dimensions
34.5,19.5 to 0,0 on Mechanical Drawing
4.85,72.1 to 0,0 on Mechanical Drawing
41.6,6.6 to 0,0 on Mechanical Drawing
5.15,13 to 0,0 on Mechanical Drawing
68.04,86.3 to 70,0 on Mechanical Drawing
1.9,86.3 to 0,95 on Mechanical Drawing
34.5,19.5 to 34.9,69.8 on Mechanical Drawing
70,0 to 70,95 on Mechanical Drawing
3.5,3.5 to 3.5,91.5 on Mechanical Drawing
66.5,3.5 to 70,0 on Mechanical Drawing
3.5,3.5 to 66.5,3.5 on Mechanical Drawing
3.5,91.5 to 0,95 on Mechanical Drawing
1.9,86.3 to 0,0 on Mechanical Drawing
65.5,64.1 to 0,0 on Mechanical Drawing
14.5,28 to 61,62.5 on Mechanical Drawing
4.3,62.9 to 0,0 on Mechanical Drawing
4.3,53.1 to 0,0 on Mechanical Drawing
4.3,43.3 to 0,0 on Mechanical Drawing
4.3,12.6 to 0,0 on Mechanical Drawing
3.8,63.4 to 0,95 on Mechanical Drawing
16.2,76.353 to 0,95 on Mechanical Drawing
2.5,19.8 to 0,0 on Mechanical Drawing
3.2,29.51 to 0,0 on Mechanical Drawing
14.5,28 to 70,0 on Mechanical Drawing
34.5,19.5 to 70,0 on Mechanical Drawing
68.4,8.06 to 70,0 on Mechanical Drawing
59.1,69.8 to 34.9,69.8 on Mechanical Drawing
34.9,69.8 to 0,95 on Mechanical Drawing
2.5,19.78 to 0,0 on Mechanical Drawing
68.04,86.3 to 0,95 on Mechanical Drawing
65.5,64.1 to 9.62,64.1 on Mechanical Drawing
9.62,64.1 to 0,95 on Mechanical Drawing
56,79 to 0,95 on Mechanical Drawing
36.5,83.5 to 0,95 on Mechanical Drawing
70,95 to 0,95 on Mechanical Drawing
14.5,28 to 0,0 on Mechanical Drawing
61,62.5 to 14.5,28 on Mechanical Drawing
59.5,19.5 to 0,0 on Mechanical Drawing
68.4,8.06 to 0,0 on Mechanical Drawing
57.9,12.6 to 0,0 on Mechanical Drawing
39.55,2.1 to 0,0 on Mechanical Drawing
24.9,2.65 to 0,0 on Mechanical Drawing
12.4,12.1 to 0,0 on Mechanical Drawing
61,62.5 to 56.57,58.07 on Mechanical Drawing
3.5,3.5 to 9.147,9.147 on Mechanical Drawing
8.4,38.9 to -5.8,40.8 on Mechanical 16
66.5,91.5 to 63.867,88.867 on Mechanical Drawing
3.5,91.5 to 7,89 on Mechanical Drawing
66.5,3.5 to 61.608,8.392 on Mechanical Drawing
14.5,28 to 16.702,25.798 on Mechanical Drawing
68.66,40.1 to 76.9,42.4 on Mechanical 16
0,95 to 11.5,23 on Mechanical Drawing
11.5,72 to 63.5,72 on Mechanical Drawing
70,0 to 63.5,23 on Mechanical Drawing
63.5,23 to 63.5,72 on Mechanical Drawing
13.7,83.4 to 7.8,83.4 on Mechanical 16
